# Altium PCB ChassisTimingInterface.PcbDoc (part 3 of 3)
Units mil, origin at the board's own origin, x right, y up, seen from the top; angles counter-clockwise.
Board outline 3400 x 6000 mil, 8 copper layers (Top Layer, GND, VDD, Mid-Layer 1, VCCAUX, Mid-Layer 2, MidLayer3, Bottom Layer), stack 62.1 mil thick; 229 components, 254 nets, 1249 pads, 708 vias.
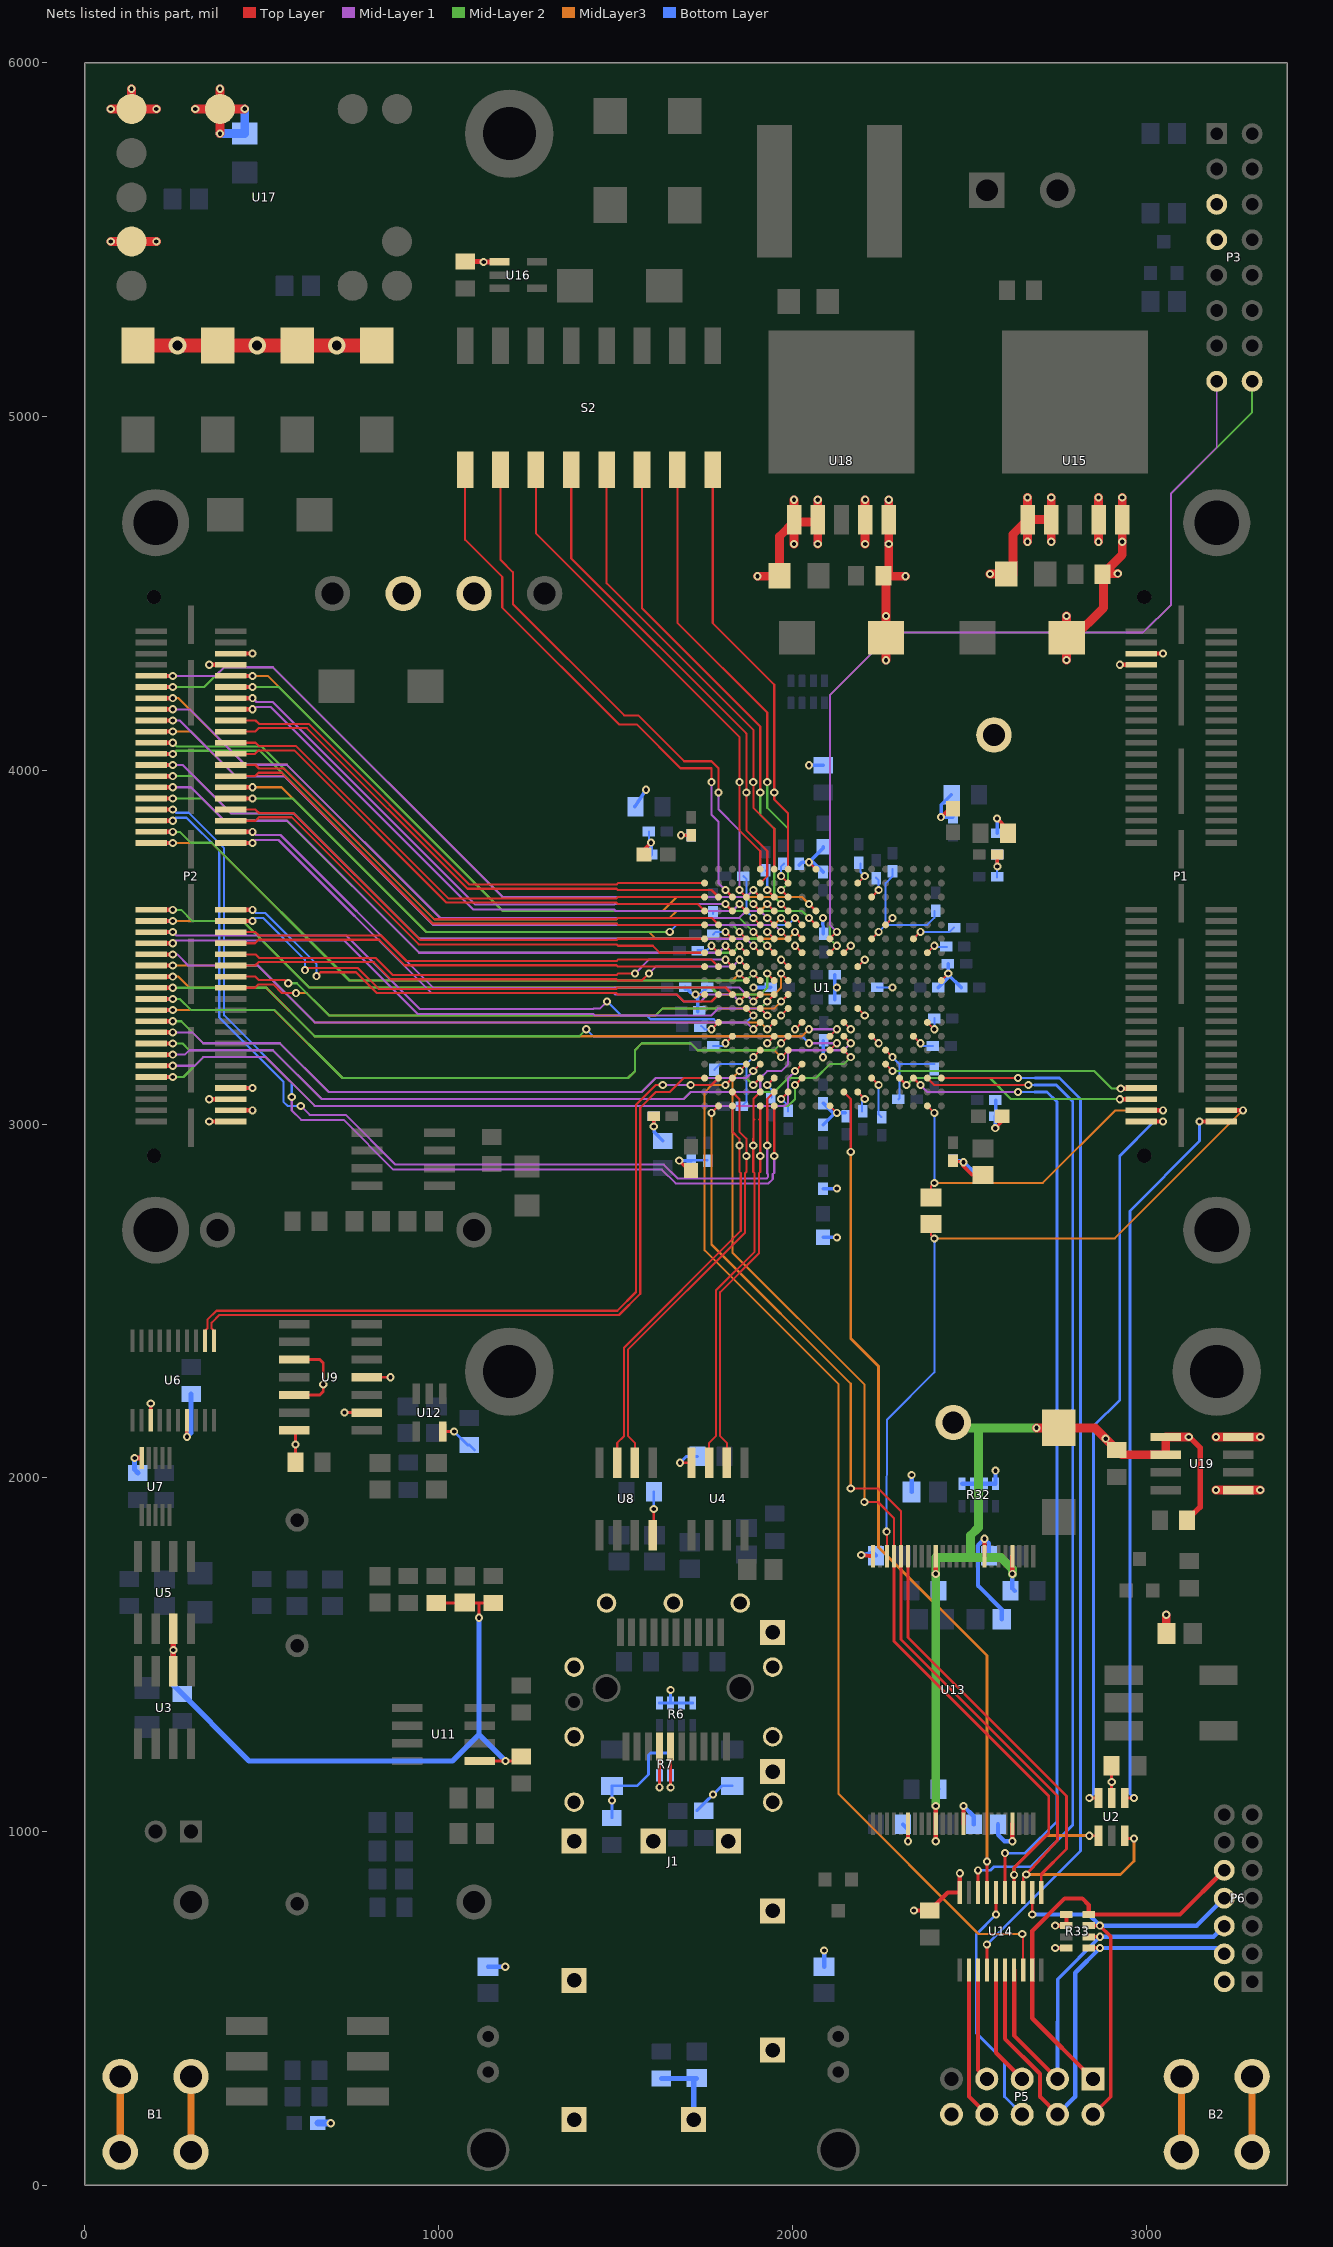
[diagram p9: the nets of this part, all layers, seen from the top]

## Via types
v1: diameter 23, hole 12, Top Layer to Bottom Layer, 669 vias
v2: diameter 23, hole 12.01, Top Layer to Bottom Layer, 33 vias
v3: diameter 50, hole 28, Top Layer to Bottom Layer, 6 vias

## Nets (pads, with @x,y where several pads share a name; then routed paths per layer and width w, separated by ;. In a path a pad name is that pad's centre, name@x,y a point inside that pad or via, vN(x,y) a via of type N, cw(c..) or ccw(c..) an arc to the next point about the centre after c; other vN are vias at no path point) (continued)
S33_48.S37_N: P2.27 U1.J13 | length 1605.9
  Top Layer w6: P2.27@412.78,3416.55 482.43,3416.55 492.18,3406.8 565,3406.8 573.8,3398 v1(574.8,3398) ; v1(1929.15,3346.46) U1.J13@1948.84,3366.14
  Mid-Layer 2 w6: v1(574.8,3398) 599.09,3398 690,3307.09 1515.75,3307.09 1535.43,3307.09 1614.17,3307.09 1633.86,3326.77 1909.47,3326.77 v1(1929.15,3346.46)
S33_48.S37_P: P2.25 U1.J12 | length 1648.7
  Top Layer w6: P2.25@412.78,3385.05 481.07,3385.05 490.82,3394.8 532.38,3394.8 557.18,3370 v1(596.8,3370) ; v1(1968.52,3346.46) U1.J12@1988.21,3366.14
  Mid-Layer 2 w6: v1(596.8,3370) v1@605.26,3370
  MidLayer3 w6: v1(596.8,3370) 627.09,3370 690,3307.09 1515.75,3307.09 1535.43,3307.09 1614.17,3307.09 1633.86,3326.77 1948.84,3326.77 v1(1968.52,3346.46)
S33_48.S38_N: P2.29 U1.L15 | length 1515.6
  Top Layer w6: P2.29@412.78,3448.03 481.07,3448.03 490.82,3457.78 816.58,3457.78 865.01,3409.36 1502.95,3409.36 1506.8,3405.51 1515.75,3405.51 1535.43,3405.51 1574.8,3405.51 v1(1594.49,3425.2) ; v1(1850.41,3464.57) U1.L15@1870.1,3444.88
  Mid-Layer 1 w6: v1(1594.49,3425.2) 1614.17,3444.88 1830.72,3444.88 v1(1850.41,3464.57)
S33_48.S38_P: P2.31 U1.L16 | length 1468
  Top Layer w6: P2.31@412.78,3479.53 482.43,3479.53 492.18,3469.78 821.56,3469.78 869.98,3421.36 1502.95,3421.36 1506.79,3425.2 ; 1506.89,3425.2 1515.75,3425.2 1535.43,3425.2 v1(1555.12,3425.2) ; v1(1811.04,3464.57) U1.L16@1830.73,3444.88
  Mid-Layer 1 w6: v1(1555.12,3425.2) 1594.5,3464.57 v1(1811.04,3464.57)
S33_48.S39_N: P2.35 U1.L17 | length 1422.1
  Top Layer w6: P2.35@412.78,3542.53 482.43,3542.53 492.18,3532.78 837.3,3532.78 909.26,3460.82 1502.95,3460.82 ; 1502.95,3460.73 1506.79,3464.57 ; 1506.89,3464.57 1515.75,3464.57 1535.43,3464.57 1771.67,3464.57 U1.L17@1791.36,3444.88
S33_48.S39_P: P2.33 U1.L18 | length 1374.6
  Top Layer w6: P2.33@412.78,3511.03 481.07,3511.03 490.82,3520.78 832.32,3520.78 904.29,3448.82 1502.95,3448.82 ; 1502.95,3448.73 1506.8,3444.88 1515.75,3444.88 1535.43,3444.88 U1.L18@1751.99,3444.88
S33_48.S40_N: P2.37 U1.J16 | length 1536.6
  Top Layer w6: v1(622,3435) 628.13,3441.13 771.46,3441.13 830.61,3381.99 1502.95,3381.99 1506.79,3385.83 ; 1506.89,3385.83 1515.75,3385.83 1535.43,3385.83 1811.04,3385.83 U1.J16@1830.73,3366.14
  Top Layer w12: P2.37@412.78,3574.02 v1(473.98,3574.02)
  Bottom Layer w6: v1(473.98,3574.02) 482.52,3582.55 503.95,3582.55 622,3464.5 v1(622,3435)
S33_48.S40_P: P2.39 U1.J17 | length 1522.8
  Top Layer w6: v1(655,3418) 666.13,3429.13 766.49,3429.13 825.64,3369.99 1502.95,3369.99 1506.8,3366.14 1515.75,3366.14 1535.43,3366.14 1673.23,3366.14 1692.91,3346.46 1771.67,3346.46 U1.J17@1791.36,3366.14
  Top Layer w12: P2.39@412.78,3605.52 v1(473.98,3605.52)
  Bottom Layer w6: v1(473.98,3605.52) 482.95,3596.55 509.75,3596.55 655,3451.3 v1(655,3418)
S33_48.S41_N: P2.43 U1.J14 | length 1704.9
  Top Layer w6: v1(1889.78,3346.46) U1.J14@1909.47,3366.14
  Top Layer w12: P2.43@412.78,3825.98 v1(473.98,3825.98)
  Mid-Layer 1 w6: v1(473.98,3825.98) 482.97,3817 553.08,3817 986,3384.08 1496.06,3384.08 1497.81,3385.83 1515.75,3385.83 1535.43,3385.83 1850.41,3385.83 v1(1889.78,3346.46)
S33_48.S41_P: P2.41 U1.J15 | length 1674.4
  Top Layer w6: v1(1850.41,3346.46) U1.J15@1870.1,3366.14
  Top Layer w12: P2.41@412.78,3794.48 v1(473.98,3794.48)
  Mid-Layer 1 w6: v1(473.98,3794.48) 482.5,3803 547.28,3803 980.2,3370.08 1496.06,3370.08 1500,3366.14 1515.75,3366.14 1535.43,3366.14 1673.23,3366.14 1692.91,3346.46 1741.46,3346.46 1761.14,3366.14 1830.72,3366.14 v1(1850.41,3346.46)
S33_48.S42_N: P2.45 U1.M18 | length 1501.9
  Top Layer w6: P2.45@412.78,3857.47 482.43,3857.47 492.18,3867.22 584.32,3867.22 943.75,3507.78 1502.95,3507.78 1506.8,3503.94 1515.75,3503.94 1535.43,3503.94 1555.12,3503.94 1605.32,3503.93 1625,3484.25 U1.M18@1751.99,3484.25
S33_48.S42_P: P2.47 U1.N18 | length 1493.6
  Top Layer w6: P2.47@412.78,3888.97 482.43,3888.97 492.18,3879.22 589.29,3879.22 948.72,3519.78 1502.95,3519.78 1506.79,3523.62 ; 1506.89,3523.62 1515.75,3523.62 1535.44,3523.62 U1.N18@1751.99,3523.62
S33_48.S43_N: P2.51 U1.N11 | length 1808.5
  Top Layer w6: v1(2007.89,3543.31) U1.N11@2027.58,3523.62
  Top Layer w12: P2.51@412.78,3951.97 v1(473.98,3951.97)
  MidLayer3 w6: v1(473.98,3951.97) 555.91,3951.97 964.57,3543.31 1515.75,3543.31 1535.43,3543.31 1594.49,3543.31 1614.17,3523.62 1988.21,3523.62 v1(2007.89,3543.31)
S33_48.S43_P: P2.49 U1.P11 | length 1795.5
  Top Layer w6: v1(2007.89,3582.68) U1.P11@2027.58,3562.99
  Top Layer w12: P2.49@412.78,3920.47 v1(473.98,3920.47)
  Mid-Layer 2 w6: v1(473.98,3920.47) 587.41,3920.47 964.57,3543.31 1515.75,3543.31 1535.43,3543.31 v1(1653.54,3543.31)
  Bottom Layer w6: v1(1653.54,3543.31) 1673.23,3562.99 1988.21,3562.99 v1(2007.89,3582.68)
S33_48.S44_N: P2.53 U1.P18 | length 1521.4
  Top Layer w6: P2.53@412.78,3983.45 481.07,3983.45 490.82,3993.2 556.76,3993.2 983.12,3566.84 1502.95,3566.84 1506.8,3562.99 1515.75,3562.99 1535.43,3562.99 U1.P18@1751.99,3562.99
S33_48.S44_P: P2.55 U1.P17 | length 1568.9
  Top Layer w6: P2.55@412.78,4014.95 482.43,4014.95 492.18,4005.2 561.73,4005.2 988.09,3578.84 1502.95,3578.84 1506.79,3582.68 ; 1506.89,3582.68 1515.75,3582.68 1535.43,3582.68 1771.67,3582.68 U1.P17@1791.36,3562.99
S33_48.S45_N: P2.59 U1.T18 | length 1523
  Top Layer w6: P2.59@412.78,4077.95 482.43,4077.95 492.18,4068.2 597.15,4068.2 1027.46,3637.89 1502.95,3637.89 1506.79,3641.73 ; 1506.89,3641.73 1515.75,3641.73 1535.43,3641.73 1584.65,3641.73 U1.T18@1751.99,3641.73
S33_48.S45_P: P2.57 U1.R18 | length 1596.2
  Top Layer w6: P2.57@412.78,4046.45 481.07,4046.45 490.82,4056.2 592.18,4056.2 1022.49,3625.89 1502.95,3625.89 1506.8,3622.05 1515.75,3622.05 1535.43,3622.04 1732.31,3622.04 U1.R18@1751.99,3602.36 ; 1539.37,3622.05 1604.33,3622.05
S33_48.S46_N: P2.61 U1.T17 | length 1629.6
  Top Layer w6: P2.61@412.78,4109.43 481.07,4109.43 490.82,4119.18 627.63,4119.18 1081.55,3665.26 1502.95,3665.26 1506.8,3661.42 1515.75,3661.42 1535.43,3661.42 1604.33,3661.42 ; 1555.12,3661.42 1771.67,3661.42 U1.T17@1791.36,3641.73
S33_48.S46_P: P2.63 U1.U18 | length 1532.8
  Top Layer w6: P2.63@412.78,4140.93 482.43,4140.93 492.18,4131.18 632.6,4131.18 1086.52,3677.26 1502.95,3677.26 1506.79,3681.1 ; 1506.89,3681.1 1515.75,3681.1 1535.43,3681.1 U1.U18@1751.99,3681.1
S33_48.S47_N: P2.67 U1.R16 | length 1668.6
  Top Layer w6: v1(1811.04,3622.05) U1.R16@1830.73,3602.36
  Top Layer w12: P2.67@412.78,4203.93 v1(473.98,4203.93)
  Mid-Layer 1 w6: v1(473.98,4203.93) 485,4192.91 531.5,4192.91 1104.11,3620.3 1496.06,3620.3 1497.81,3622.05 1515.75,3622.05 1535.43,3622.05 v1(1811.04,3622.05)
S33_48.S47_P: P2.65 U1.R15 | length 1715.1
  Top Layer w6: v1(1850.41,3622.05) U1.R15@1870.1,3602.36
  Top Layer w12: P2.65@412.78,4172.43 v1(473.98,4172.43)
  Mid-Layer 1 w6: v1(473.98,4172.43) 480.46,4178.91 525.7,4178.91 1098.31,3606.3 1496.06,3606.3 1500,3602.36 1515.75,3602.36 1535.43,3602.36 1830.73,3602.36 v1(1850.41,3622.05)
S33_48.S48_N: P2.69 U1.P10 | length 1932.7
  Top Layer w6: v1(2047.26,3582.68) U1.P10@2066.95,3562.99
  Top Layer w12: P2.69@412.78,4235.42 v1(473.98,4235.42)
  Mid-Layer 2 w6: v1(473.98,4235.42) 548.05,4235.42 1181.1,3602.36 1515.75,3602.36 1535.43,3602.36 2027.57,3602.36 v1(2047.26,3582.68)
S33_48.S48_P: P2.71 U1.R10 | length 1962
  Top Layer w6: v1(2047.26,3622.05) U1.R10@2066.95,3602.36
  Top Layer w12: P2.71@412.78,4266.92 v1(473.98,4266.92)
  MidLayer3 w6: v1(473.98,4266.92) 516.55,4266.92 1181.1,3602.36 1515.75,3602.36 1535.43,3602.36 1633.86,3602.36 1673.23,3641.73 2027.57,3641.73 v1(2047.26,3622.05)
S49_64.S49_N: P2.12 U1.D11 | length 1997.4
  Top Layer w6: v1(2007.89,3149.61) U1.D11@2027.58,3169.29
  Top Layer w12: P2.12@187.22,3164.58 v1(248.42,3164.58)
  Mid-Layer 1 w6: v1(248.42,3164.58) 310.25,3164.58 334.65,3188.98 511.81,3188.98 649.61,3051.18 1515.75,3051.18 1535.43,3051.18 1979.33,3051.18 1988.19,3060.04 1988.19,3129.9 v1(2007.89,3149.61)
S49_64.S49_P: P2.10 U1.C11 | length 1976.3
  Top Layer w6: v1(2007.89,3110.24) U1.C11@2027.58,3129.92
  Top Layer w12: P2.10@187.22,3133.08 v1(248.42,3133.08)
  Mid-Layer 2 w6: v1(248.42,3133.08) 278.75,3133.08 334.65,3188.98 511.81,3188.98 649.61,3051.18 1515.75,3051.18 1535.43,3051.18 1988.19,3051.18 2007.89,3070.88 v1(2007.89,3110.24)
S49_64.S50_N: P2.14 U1.F8 | length 2168.9
  Top Layer w6: U1.F8@2145.69,3248.03 v1(2165.37,3228.35)
  Top Layer w12: P2.14@187.22,3196.07 v1(248.42,3196.07)
  Mid-Layer 1 w6: v1(248.42,3196.07) 282.68,3196.07 295.28,3208.66 531.5,3208.66 669.29,3070.87 1515.75,3070.87 1535.43,3070.87 1692.91,3070.87 1712.6,3090.55 1900.59,3090.55 1909.45,3099.41 1909.45,3129.92 1929.13,3149.61 1968.52,3149.61 1988.19,3169.29 1988.19,3199.19 1997.66,3208.66 2145.67,3208.66 v1(2165.37,3228.35)
S49_64.S50_P: P2.16 U1.E8 | length 2119.8
  Top Layer w6: U1.E8@2145.69,3208.66 v1(2165.36,3188.98)
  Top Layer w12: P2.16@187.22,3227.57 v1(248.42,3227.57)
  Mid-Layer 2 w6: v1(248.42,3227.57) 276.37,3227.57 295.28,3208.66 531.5,3208.66 669.29,3070.87 1515.75,3070.87 1535.43,3070.87 1692.91,3070.87 1712.6,3090.55 1948.84,3090.55 1988.21,3129.92 2066.93,3129.92 2106.3,3169.29 2145.67,3169.29 v1(2165.36,3188.98)
S49_64.S51_N: P2.20 U1.C14 | length 1837.7
  Top Layer w6: v1(1889.76,3110.24) U1.C14@1909.45,3129.92
  Top Layer w12: P2.20@187.22,3290.57 v1(248.42,3290.57)
  Mid-Layer 2 w6: v1(248.42,3290.57) 272.43,3290.57 334.65,3228.35 551.18,3228.35 688.98,3090.55 1515.75,3090.55 1535.43,3090.55 1574.8,3090.55 1614.17,3129.92 1870.08,3129.92 v1(1889.76,3110.24)
S49_64.S51_P: P2.18 U1.D14 | length 1824.6
  Top Layer w6: v1(1889.76,3149.61) U1.D14@1909.45,3169.29
  Top Layer w12: P2.18@187.22,3259.07 v1(248.42,3259.07)
  Mid-Layer 1 w6: v1(248.42,3259.07) 303.93,3259.07 334.65,3228.35 551.18,3228.35 688.98,3090.55 1515.75,3090.55 1535.43,3090.55 1574.8,3090.55 1614.17,3129.92 1870.08,3129.92 v1(1889.76,3149.61)
S49_64.S52_N: P2.22 U1.E12 | length 1980.4
  Top Layer w6: v1(1968.5,3188.98) U1.E12@1988.19,3208.66
  Top Layer w12: P2.22@187.22,3322.05 v1(248.42,3322.05)
  MidLayer3 w6: v1(248.42,3322.05) 536.22,3322.05 728.35,3129.92 1515.75,3129.92 1535.43,3129.92 1555.12,3149.61 1555.12,3208.66 1574.8,3228.35 1712.6,3228.35 1732.28,3208.66 1948.82,3208.66 v1(1968.5,3188.98)
S49_64.S52_P: P2.24 U1.F12 | length 1993.4
  Top Layer w6: v1(1968.52,3228.35) U1.F12@1988.21,3248.03
  Top Layer w12: P2.24@187.22,3353.55 v1(248.42,3353.55)
  Mid-Layer 2 w6: v1(248.42,3353.55) 268.5,3353.55 300.2,3321.85 536.42,3321.85 728.35,3129.92 1515.75,3129.92 1535.43,3129.92 1555.12,3149.61 1555.12,3208.66 1574.8,3228.35 1712.6,3228.35 1732.28,3208.66 1948.84,3208.66 v1(1968.52,3228.35)
S49_64.S53_N: P2.28 U1.F9 | length 2044.6
  Top Layer w6: U1.F9@2106.32,3248.03 v1(2126,3267.72)
  Top Layer w12: P2.28@187.22,3416.55 v1(248.42,3416.55)
  Mid-Layer 1 w6: v1@2047.24,3267.72 v1(2126,3267.72)
  MidLayer3 w6: v1(248.42,3416.55) 264.55,3416.55 295.28,3385.83 511.81,3385.83 649.61,3248.03 1515.75,3248.03 1535.43,3248.03 2027.58,3248.03 v1(2047.26,3267.72)
S49_64.S53_P: P2.26 U1.E9 | length 2047.8
  Top Layer w6: U1.E9@2106.32,3208.66 v1(2126,3228.35)
  Top Layer w12: P2.26@187.22,3385.05 v1(248.42,3385.05)
  Mid-Layer 1 w6: v1(2047.26,3228.35) v1(2126,3228.35)
  Mid-Layer 2 w6: v1(248.42,3385.05) 512.59,3385.05 649.61,3248.03 1397.64,3248.03 v1(1417.32,3267.72)
  Bottom Layer w6: v1(1417.32,3267.72) 1437.01,3248.03 1515.75,3248.03 1535.43,3248.03 2027.57,3248.03 v1(2047.26,3228.35)
S49_64.S54_N: P2.30 U1.G13 | length 1844.5
  Top Layer w6: v1(1929.15,3267.72) U1.G13@1948.84,3287.4
  Top Layer w12: P2.30@187.22,3448.03 v1(248.42,3448.03)
  MidLayer3 w6: v1(248.42,3448.03) 488.97,3448.03 649.61,3287.4 1515.75,3287.4 1535.43,3287.4 1909.46,3287.4 v1(1929.15,3267.72)
S49_64.S54_P: P2.32 U1.G14 | length 1818.1
  Top Layer w6: v1(1889.78,3267.72) U1.G14@1909.47,3287.4
  Top Layer w12: P2.32@187.22,3479.53 v1(248.42,3479.53)
  Mid-Layer 1 w6: v1(248.42,3479.53) 260.62,3479.53 292.16,3448 489.01,3448 649.61,3287.4 1515.75,3287.4 1535.43,3287.4 1870.09,3287.4 v1(1889.78,3267.72)
S49_64.S55_N: P2.36 U1.H15 | length 1862
  Top Layer w6: U1.H15@1870.1,3326.77 v1(1889.78,3307.09)
  Top Layer w12: P2.36@187.22,3542.53 v1(248.42,3542.53)
  Mid-Layer 1 w6: v1(248.42,3542.53) 257.95,3533 738.65,3533 946.63,3325.02 1437.01,3325.02 1438.76,3326.77 1456.69,3326.77 v1(1476.38,3346.46)
  Bottom Layer w6: v1(1476.38,3346.46) 1515.75,3307.09 1535.43,3307.09 1587.91,3307.09 1599,3296 1778,3296 1786.6,3287.4 1870.1,3287.4 v1(1889.78,3307.09)
S49_64.S55_P: P2.34 U1.H14 | length 1877.2
  Top Layer w6: U1.H14@1909.47,3326.77 v1(1929.15,3307.09)
  Top Layer w12: P2.34@187.22,3511.03 v1(248.42,3511.03)
  Mid-Layer 1 w6: v1(248.42,3511.03) 256.38,3519 732.85,3519 940.83,3311.02 1437.01,3311.02 1440.94,3307.09 1456.69,3307.09 1515.75,3307.09 1535.43,3307.09 1771.65,3307.09 1791.34,3326.77 1909.47,3326.77 v1(1929.15,3307.09)
S49_64.S56_N: P2.38 U1.K12 | length 1942.8
  Top Layer w6: v1(1968.52,3425.2) U1.K12@1988.21,3405.51
  Top Layer w12: P2.38@187.22,3574.02 v1(248.42,3574.02)
  MidLayer3 w6: v1(248.42,3574.02) 445.98,3574.02 634.17,3385.83 1515.75,3385.83 1535.43,3385.83 1771.65,3385.83 1791.34,3366.14 1948.82,3366.14 1968.52,3385.84 v1(1968.52,3425.2)
S49_64.S56_P: P2.40 U1.K13 | length 1916.4
  Top Layer w6: v1(1929.15,3425.2) U1.K13@1948.84,3405.51
  Top Layer w12: P2.40@187.22,3605.52 v1(248.42,3605.52)
  Mid-Layer 2 w6: v1(248.42,3605.52) 272.44,3605.52 303.94,3574.02 445.98,3574.02 634.17,3385.83 1515.75,3385.83 1535.43,3385.83 1771.65,3385.83 1791.34,3366.14 1909.45,3366.14 1929.15,3385.84 v1(1929.15,3425.2)
S49_64.S57_N: P2.44 U1.K14 | length 1912.7
  Top Layer w6: v1(1889.78,3425.2) U1.K14@1909.47,3405.51
  Top Layer w12: P2.44@187.22,3825.98 v1(248.42,3825.98)
  Mid-Layer 2 w6: v1(248.42,3825.98) 268.5,3825.98 299.49,3795 358.54,3795 748.03,3405.51 1515.75,3405.51 1535.43,3405.51 1870.1,3405.51 v1(1889.78,3425.2)
S49_64.S57_P: P2.42 U1.K15 | length 1860.3
  Top Layer w6: v1(1850.41,3425.2) U1.K15@1870.1,3405.51
  Top Layer w12: P2.42@187.22,3794.48 v1(248.42,3794.48)
  MidLayer3 w6: v1(248.42,3794.48) 359.06,3794.48 748.03,3405.51 1515.75,3405.51 1535.43,3405.51 1830.73,3405.51 v1(1850.41,3425.2)
S49_64.S58_N: P2.46 U1.B13 | length 2730.9
  Top Layer w6: v1(1929.13,2938.97) 1929.13,3070.85 U1.B13@1948.84,3090.55
  Top Layer w12: P2.46@187.22,3857.47 v1(248.42,3857.47)
  Mid-Layer 1 w6: v1(610.24,3051.18) 635.61,3025.81 737.19,3025.81 878,2885 1637,2885 1676,2846 1927,2846 1930.88,2849.88 1930.88,2858.27 1929.13,2860.02 1929.13,2877.95 1929.13,2893.7 v1(1929.13,2938.97)
  Bottom Layer w6: v1(248.42,3857.47) 256.95,3866 287.43,3866 379.7,3773.73 379.7,3301.29 560.97,3120.02 560.97,3088.03 ; 561,3088 561,3063 572.82,3051.18 v1(610.24,3051.18)
S49_64.S58_P: P2.48 U1.A13 | length 2731.5
  Top Layer w6: v1(1948.81,2909.44) U1.A13@1948.84,3051.18
  Top Layer w12: P2.48@187.22,3888.97 v1(248.42,3888.97)
  Mid-Layer 1 w6: v1(584.87,3076.55) 584.87,3038.13 611.19,3011.81 731.39,3011.81 872.2,2871 1631.2,2871 1670.2,2832 1932.8,2832 1944.88,2844.08 1944.88,2858.27 1948.82,2862.2 1948.82,2877.95 1948.81,2893.71 v1(1948.81,2909.44)
  Bottom Layer w6: v1(248.42,3888.97) 257.38,3880 293.23,3880 393.7,3779.53 393.7,3307.09 584.87,3115.92 v1(584.87,3076.55)
S49_64.S59_N: P2.52 U1.M16 | length 1853.6
  Top Layer w6: v1(1811.04,3503.94) U1.M16@1830.73,3484.25
  Top Layer w12: P2.52@187.22,3951.97 v1(248.42,3951.97)
  Mid-Layer 1 w6: v1(248.42,3951.97) 300,3951.97 394.5,3857.47 571.67,3857.47 944.88,3484.25 1515.75,3484.25 1535.43,3484.25 1791.36,3484.25 v1(1811.04,3503.94)
S49_64.S59_P: P2.50 U1.M15 | length 1879.9
  Top Layer w6: v1(1850.41,3503.94) U1.M15@1870.1,3484.25
  Top Layer w12: P2.50@187.22,3920.47 v1(248.42,3920.47)
  Mid-Layer 2 w6: v1(248.42,3920.47) 331.5,3920.47 393.7,3858.27 570.87,3858.27 944.88,3484.25 1515.75,3484.25 1535.43,3484.25 1830.73,3484.25 v1(1850.41,3503.94)
S49_64.S60_N: P2.54 U1.M13 | length 1968.4
  Top Layer w6: v1(1929.15,3503.94) U1.M13@1948.84,3484.25
  Top Layer w12: P2.54@187.22,3983.45 v1(248.42,3983.45)
  Mid-Layer 2 w6: v1(248.42,3983.45) 307.89,3983.45 413.39,3877.95 590.55,3877.95 944.88,3523.62 1515.75,3523.62 1535.43,3523.62 1909.47,3523.62 v1(1929.15,3503.94)
S49_64.S60_P: P2.56 U1.M14 | length 1942.1
  Top Layer w6: v1(1889.78,3503.94) U1.M14@1909.47,3484.25
  Top Layer w12: P2.56@187.22,4014.95 v1(248.42,4014.95)
  Mid-Layer 1 w6: v1(248.42,4014.95) 276.39,4014.95 413.39,3877.95 590.55,3877.95 944.88,3523.62 1515.75,3523.62 1535.43,3523.62 1870.09,3523.62 v1(1889.78,3503.94)
S49_64.S61_N: P2.60 U1.N14 | length 1955
  Top Layer w6: v1(1889.78,3543.31) U1.N14@1909.47,3523.62
  Top Layer w12: P2.60@187.22,4077.95 v1(248.42,4077.95)
  Mid-Layer 2 w6: v1(248.42,4077.95) 259.25,4067.12 499.81,4067.12 988.09,3578.84 1502.95,3578.84 1506.79,3582.68 1515.75,3582.68 1535.43,3582.68 1850.41,3582.68 v1(1889.78,3543.31)
S49_64.S61_P: P2.58 U1.N15 | length 1906.6
  Top Layer w6: v1(1850.41,3543.31) U1.N15@1870.1,3523.62
  Top Layer w12: P2.58@187.22,4046.45 v1(248.42,4046.45)
  Mid-Layer 2 w6: v1(248.42,4046.45) 257.08,4055.12 494.84,4055.12 983.12,3566.84 1502.95,3566.84 1506.8,3562.99 1515.75,3562.99 1535.43,3562.99 1830.72,3562.99 v1(1850.41,3543.31)
S49_64.S62_N: P2.62 U1.P12 | length 2043.6
  Top Layer w6: v1(1968.52,3582.68) U1.P12@1988.21,3562.99
  Top Layer w12: P2.62@187.22,4109.43 v1(248.42,4109.43)
  MidLayer3 w6: v1(248.42,4109.43) 300.02,4109.43 426,3983.45 563.79,3983.45 984.25,3562.99 1515.75,3562.99 1535.43,3562.99 1948.84,3562.99 v1(1968.52,3582.68)
S49_64.S62_P: P2.64 U1.N12 | length 2056.7
  Top Layer w6: v1(1968.52,3543.31) U1.N12@1988.21,3523.62
  Top Layer w12: P2.64@187.22,4140.93 v1(248.42,4140.93)
  Mid-Layer 1 w6: v1(248.42,4140.93) 268.52,4140.93 426.45,3983 564.24,3983 984.25,3562.99 1515.75,3562.99 1535.43,3562.99 1948.83,3562.99 v1(1968.52,3543.31)
S49_64.S63_N: P2.68 U1.R13 | length 2043.4
  Top Layer w6: v1(1929.15,3622.05) U1.R13@1948.84,3602.36
  Top Layer w12: P2.68@187.22,4203.93 v1(248.42,4203.93)
  MidLayer3 w6: v1(248.42,4203.93) 264.57,4203.93 452.76,4015.75 570.87,4015.75 1003.94,3582.68 1515.75,3582.68 1535.43,3582.68 1653.54,3582.68 1673.23,3602.36 1909.47,3602.36 v1(1929.15,3622.05)
S49_64.S63_P: P2.66 U1.P13 | length 2030.4
  Top Layer w6: v1(1929.15,3582.68) U1.P13@1948.84,3562.99
  Top Layer w12: P2.66@187.22,4172.43 v1(248.42,4172.43)
  Mid-Layer 1 w6: v1(248.42,4172.43) 296.07,4172.43 452.76,4015.75 570.87,4015.75 1003.94,3582.68 1515.75,3582.68 1535.43,3582.68 1850.39,3582.68 1870.08,3602.36 1909.46,3602.36 v1(1929.15,3582.68)
S49_64.S64_N: P2.70 U1.R14 | length 2030.8
  Top Layer w6: v1(1889.78,3622.05) U1.R14@1909.47,3602.36
  Top Layer w12: P2.70@187.22,4235.42 v1(248.42,4235.42)
  Mid-Layer 2 w6: v1(248.42,4235.42) 337.78,4235.42 393.7,4291.34 531.5,4291.34 1181.1,3641.73 1515.75,3641.73 1535.43,3641.73 1870.09,3641.73 v1(1889.78,3622.05)
S49_64.S64_P: P2.72 U1.T14 | length 2017.7
  Top Layer w6: v1(1889.78,3661.42) U1.T14@1909.47,3641.73
  Top Layer w12: P2.72@187.22,4266.92 v1(248.42,4266.92)
  Mid-Layer 1 w6: v1(248.42,4266.92) 369.28,4266.92 393.7,4291.34 531.5,4291.34 1181.1,3641.73 1515.75,3641.73 1535.43,3641.73 1870.1,3641.73 v1(1889.78,3661.42)
SCL: J1.5 R7.1 | length 151
  Top Layer w8: v1(1656,1124) J1.5@1655.98,1240
  Bottom Layer w8: v1(1656,1124) R7.1@1656,1159
SDA: J1.4 R7.2 | length 150
  Top Layer w8: v1(1624.49,1124.49) J1.4@1624.49,1240
  Bottom Layer w8: v1(1624.49,1124.49) R7.2@1624.5,1159
SH0: B1.0 B2.0 C11.1 J1.21 J1.22 R8.1 | length 1075.1
  MidLayer3 w20: B1.0@100,93 B1.0@100,307 ; B1.0@300,93 B1.0@300,307 ; B2.0@3100,93 B2.0@3100,307 ; B2.0@3300,93 B2.0@3300,307
  Bottom Layer w8: R8.1@1720.94,293.54 R8.1@1729.02,301.61
  Bottom Layer w15: C11.1@1630,301.61 R8.1@1729.02,301.61 ; J1.21@1720.94,184.88 R8.1@1720.94,293.54
STCK: U1.B8 U14.17 | length 2430.9
  Top Layer w6: U1.B8@2145.69,3090.55 2165.37,3070.87 v1(2165.35,2921.26)
  Top Layer w8: U14.17@2550.39,827.24 v2(2550.39,914.61)
  MidLayer3 w6: 2165.35,2846.46 2165.35,2866.14 v1(2165.35,2921.26)
  MidLayer3 w8: 2165.35,2846.46 2165.35,2393.7 2244.09,2314.96 2244.09,1803.15 2550.39,1496.85 v2(2550.39,914.61)
STCK_EXT: P5.7 U14.3 | length 319.2
  Top Layer w12: U14.3@2524.8,608.74 2524.8,325.2 P5.7@2550,300
STDI: U1.C3 U14.15 | length 2762.9
  Top Layer w6: U1.C3@2342.54,3129.92 v1(2362.22,3110.24)
  Top Layer w8: U14.15@2601.58,827.24 v1(2601.58,938.42)
  Mid-Layer 1 w6: v1(2362.22,3110.24) 2381.91,3090.55 v1(2637.8,3090.55)
  Bottom Layer w6: v1(2637.8,3090.55) 2685.04,3090.55
  Bottom Layer w8: v1(2601.58,938.42) 2658.42,938.42 2748,1028 2748,3063.02 2720.47,3090.55 2704.72,3090.55 2685.04,3090.55
STDI_EXT: P5.5 U14.5 | length 339.4
  Top Layer w12: U14.5@2575.98,608.74 2575.98,374.02 P5.5@2650,300
STDO: U1.C1 U14.4 | length 2989.7
  Top Layer w6: U1.C1@2421.28,3129.92 v1(2637.79,3129.92)
  Top Layer w8: U14.4@2550,609.13 v2(2550,680)
  Bottom Layer w6: v1(2637.79,3129.92) 2687.01,3129.92
  Bottom Layer w8: v2(2550,680) 2815,945 2815,3070.83 2755.91,3129.92 2704.72,3129.92 2687.01,3129.92
STDO_EXT: P5.6 U14.16 | length 704.3
  Top Layer w8: v1(2575.98,764.68) U14.16@2575.98,827.24
  Bottom Layer w8: v1(2575.98,764.68) 2520,708.7 2520,430 2600,350 2600,250 P5.6@2650,200
STMS: U1.C2 U14.18 | length 2867.6
  Top Layer w6: U1.C2@2381.91,3129.92 2401.59,3110.24 v1(2667.32,3110.24)
  Top Layer w8: U14.18@2524.8,827.24 v1(2524.8,889.8)
  Bottom Layer w6: v1(2667.32,3110.24) 2685.03,3110.24
  Bottom Layer w8: v1@2525,890 2560,890 2570,900 2675,900 2793,1018 2793,3063.3 2746.06,3110.24 2704.72,3110.24 2685.03,3110.24
STMS_EXT: P5.8 U14.2 | length 429.8
  Top Layer w12: U14.2@2499.21,608.74 2499.21,250.79 P5.8@2550,200
SW1: S2.1 U1.T16 | length 1626.7
  Top Layer w6: S2.1@1075,4874.8 1075,4652 1180,4547 1180,4460 1510,4130 1560,4130 1684.09,4005.91 1771.65,4005.91 1771.65,3982.28 v1(1771.65,3966.54) ; v1(1811.04,3661.42) U1.T16@1830.73,3641.73
  Mid-Layer 1 w6: v1(1771.65,3966.54) 1771.65,3874.01 1791.33,3854.34 1791.35,3681.11 v1(1811.04,3661.42)
SW2: S2.2 U1.T15 | length 1589.7
  Top Layer w6: S2.2@1175,4874.8 1175,4595 1210,4560 1210,4470 1524.56,4155.44 1564.56,4155.44 1694.41,4025.59 1771.65,4025.59 1791.34,4005.91 1791.34,3982.28 v1(1791.34,3937.01) ; v1(1850.41,3661.42) U1.T15@1870.1,3641.73
  Mid-Layer 1 w6: v1(1791.34,3937.01) 1791.34,3889.76 1850.41,3830.69 v1(1850.41,3661.42)
SW3: S2.3 U1.V14 | length 1417.1
  Top Layer w6: S2.3@1275,4874.8 1275,4669.88 1850.39,4094.49 1850.39,4005.91 1850.39,3982.28 1850.39,3830.71 1909.47,3771.64 U1.V14@1909.47,3720.47
  other v1: 1850.39,3966.54
SW4: S2.4 U1.U14 | length 1431.2
  Top Layer w6: S2.4@1375,4874.8 1375,4599 1869.67,4104.33 ; 1870.08,4104.33 1870.08,4005.91 1870.08,3982.28 1870.08,3830.71 1929.15,3771.64 1929.15,3700.82 U1.U14@1909.47,3681.1
  other v1: 1870.08,3937.01
SW5: S2.5 U1.V13 | length 1350.6
  Top Layer w6: S2.5@1475,4874.8 1475,4528.94 1889.76,4114.17 1889.76,4005.91 1889.76,3982.28 1889.76,3893.7 1948.84,3834.63 U1.V13@1948.84,3720.47
  other v1: 1889.76,3966.54
SW6: S2.6 U1.R12 | length 1443.6
  Top Layer w6: S2.6@1575,4874.8 1575,4458.46 1909.45,4124.02 1909.45,4005.91 1909.45,3982.28 v1(1909.45,3937.01) ; v1(1968.52,3622.05) U1.R12@1988.21,3602.36
  Mid-Layer 2 w6: v1(1909.45,3937.01) 1909.45,3874.02 1948.83,3834.63 1948.83,3641.73 v1(1968.52,3622.05)
SW7: S2.7 U1.T12 | length 1379.1
  Top Layer w6: S2.7@1675,4874.8 1675,4417.52 1929.13,4163.39 1929.13,4005.91 1929.13,3982.28 v1(1929.13,3966.54) ; v1(1968.52,3661.42) U1.T12@1988.21,3641.73
  Mid-Layer 2 w6: v1(1929.13,3966.54) 1929.13,3893.7 1988.21,3834.63 1988.21,3681.1 v1(1968.52,3661.42)
SW8: S2.8 U1.V12 | length 1242.6
  Top Layer w6: S2.8@1775,4874.8 1775,4415.94 1948.82,4242.13 1948.82,4005.91 1948.82,3982.28 1948.82,3917.32 1988.21,3877.94 U1.V12@1988.21,3720.47
  other v1: 1948.82,3937.01
SW9: P1.6 U1.C4 | length 725.2
  Top Layer w6: U1.C4@2303.17,3129.92 v1(2322.84,3110.24)
  Top Layer w12: v1(2926.02,3070.08) P1.6@2987.22,3070.08
  Mid-Layer 2 w6: v1(2322.84,3110.24) 2342.52,3129.92 2559.06,3129.92 2618.11,3070.87 2925.23,3070.87 v1(2926.02,3070.08)
SW10: P1.8 U1.D5 | length 754.9
  Top Layer w6: U1.D5@2263.8,3169.29 v1(2283.48,3149.6)
  Top Layer w12: v1(2928.8,3100) P1.8@2990,3100
  Mid-Layer 2 w6: v1(2283.48,3149.6) 2854.34,3149.6 2903.94,3100 v1(2928.8,3100)
SYNC_N: U1.C17 U6.2 | length 2100
  Top Layer w6: U6.2@339.57,2387.2 339.57,2414.84 346.36,2421.64 346.36,2446.36 372,2472 1505.03,2472 1558,2524.97 1558,3054.06 1614.17,3110.24 v1(1633.86,3110.24) ; v1(1712.6,3110.24) 1771.67,3110.24 U1.C17@1791.36,3129.92
  Mid-Layer 1 w6: v1(1633.86,3110.24) v1(1712.6,3110.24)
SYNC_P: U1.C18 U6.1 | length 2042.4
  Top Layer w6: U6.1@365.16,2387.2 365.16,2414.84 358.36,2421.64 358.36,2438.36 380,2460 1510,2460 1570,2520 1570,3046.38 1614.17,3090.55 1653.54,3090.55 1692.91,3129.92 U1.C18@1751.99,3129.92
SYNCIN_N: U1.A14 U4.6 | length 1069.1
  Top Layer w6: U4.6@1815,2042.36 1815,2098.42 1796,2117.41 1796,2285.33 1796,2524.34 1905.6,2633.94 1905.6,2861.21 1909.45,2865.06 1909.45,2874.01 1909.44,2893.7 1909.44,2958.66 ; 1905.62,3012.5 1909.47,3016.34 ; 1909.47,2958.68 U1.A14@1909.47,3051.18
  other v1: 1909.44,2909.44
SYNCIN_P: U1.B14 U4.7 | length 1116.5
  Top Layer w6: U4.7@1765,2042.36 1765,2098.42 1784,2117.41 1784,2290.3 1784,2529.32 1893.6,2638.92 1893.6,2861.22 1889.76,2865.06 ; 1889.76,2865.15 1889.76,2874.01 1889.76,2893.7 1889.76,2958.66 ; 1889.78,2958.68 1889.78,3070.87 U1.B14@1909.47,3090.55 ; 1889.78,3016.34 1893.62,3012.5
  other v1: 1889.76,2938.97
SYNCLK_N: P3.16 U1.M9 | length 2541.6
  Top Layer w6: U1.M9@2106.32,3484.25 v1(2125.98,3503.94)
  Mid-Layer 2 w5: 2106.3,3996.06 2106.3,4212.6 2283.46,4389.76 2992.13,4389.76 3070.87,4468.5 3070.87,4783.46 3300,5012.6 P3.16@3300,5100
  Mid-Layer 2 w6: 2106.3,3996.06 2106.3,3976.38 2106.3,3523.62 v1(2125.98,3503.94)
SYNCLK_P: P3.15 U1.N9 | length 2460.8
  Top Layer w6: U1.N9@2106.32,3523.62 v1(2126,3543.31)
  Mid-Layer 1 w5: 2106.3,3996.06 2106.3,4212.6 2283.46,4389.76 2992.13,4389.76 3070.87,4468.5 3070.87,4783.46 3200,4912.6 P3.15@3200,5100
  Mid-Layer 1 w6: 2106.3,3996.06 2106.3,3976.38 2106.3,3563.01 v1(2126,3543.31)
SYNCOUT_N: U1.A16 U8.3 | length 1163.1
  Top Layer w6: U8.3@1505,2042.36 1505,2098.42 1524,2117.41 1524,2236.99 1524,2367.74 1854.23,2697.97 1854.23,2861.22 1850.39,2865.06 ; U1.A16@1830.73,3051.18 1830.73,2978.32 1850.39,2958.66 1850.39,2893.7 1850.39,2874.01 1850.39,2865.15
  other v1: 1850.39,2938.97
SYNCOUT_P: U1.B16 U8.2 | length 1210.8
  Top Layer w5.98: 1866.22,2692.99 1866.22,2861.22
  Top Layer w6: U8.2@1555,2042.36 1555,2098.42 1536,2117.41 1536,2232.02 1536,2362.77 1866.23,2693 ; U1.B16@1830.73,3090.55 1850.39,3070.89 1850.39,2978.34 1870.07,2958.66 1870.07,2893.7 1870.07,2874.01 1870.07,2865.06 1866.23,2861.21
  other v1: 1870.07,2909.44
TCK: U1.A17 U2.3 U13.20 U14.13 | length 3131
  Top Layer w6: v1(1771.65,3031.5) U1.A17@1791.36,3051.18 ; v1(2165.35,1969.49) 2243.11,1969.49 2307.17,1905.43 U13.20@2307.17,1777.79
  Top Layer w8: U13.20@2307.17,1777.79 2307.17,1542.83 2750,1100 2750,975 v1(2661.42,877.95) 2652.76,869.29 U14.13@2652.76,827.24 ; U2.3@2940,980 v1(2965.81,980)
  MidLayer3 w6: v1(1771.65,3031.5) 1771.65,2659.45 2165.35,2265.75 v1(2165.35,1969.49)
  MidLayer3 w8: v1(2661.42,877.95) 2927.76,877.76 2965.81,915.81 v1(2965.81,980)
TCK_B: P1.1 U2.4 | length 2086.5
  Top Layer w8: U2.4@2940.4,1094.15 v1(2966.21,1094.15)
  Top Layer w12: v1(3151.58,3007.1) P1.1@3212.78,3007.1
  Bottom Layer w8: v1(2966.21,1094.15) 2954.4,1105.96 2954.4,2754.4 3151.58,2951.58 v1(3151.58,3007.1)
TCK_EXT: P5.3 P6.6 R33.6 U14.7 | length 1207.2
  Top Layer w10: R33.6@2837.99,702.01 v1(2870,702.01)
  Top Layer w12: U14.7@2627.17,608.74 2627.17,422.83 P5.3@2750,300
  Bottom Layer w10: 2750,461.22 2750,582.01 v1(2870,702.01)
  Bottom Layer w12: P5.3@2750,300 2750,461.22 ; v1(2870,702.01) 3190.79,702.01 P6.6@3221.26,732.48
TDI_1: U13.19 U14.11 | length 1165.6
  Top Layer w8: U13.19@2326.85,1777.79 2326.85,1548.15 2775,1100 2775,950 2703.94,878.94 U14.11@2703.94,827.24
TDI_A: P1.3 R1.2 U13.22 | length 2082.9
  Top Layer w6: v1@2267.64,1847.44 2267.64,1777.95 U13.22@2267.8,1777.79 ; R1.2@2392,2717.6 2392,2686.15 v1(2401.58,2676.58)
  Top Layer w12: P1.3@3212.78,3038.58 v1(3273.98,3038.6)
  MidLayer3 w6: v1(2401.58,2676.58) 2911.96,2676.58 v1(3273.98,3038.6)
  Bottom Layer w6: v1(2266.73,1847.44) 2267.64,2164.29 2401.58,2298.23 v1(2401.58,2676.58)
TDI_B: P1.4 R1.1 U1.A2 | length 1063.9
  Top Layer w6: U1.A2@2381.91,3051.18 v1(2401.58,3031.49) ; R1.1@2392,2792.4 2392,2823.85 v1(2401.58,2833.42)
  Top Layer w12: P1.4@2987.22,3038.58 v1(3048.42,3038.6)
  MidLayer3 w6: v1(2401.58,2833.42) 2708.42,2833.42 2913.6,3038.6 v1(3048.42,3038.6)
  Bottom Layer w6: v1(2401.58,2833.42) v1(2401.58,3031.49)
TDI_EXT: P5.1 P6.10 R33.8 U14.9 | length 1156.5
  Top Layer w12: P5.1@2850,300 2678.35,471.65 2678.35,718.35 2770,810 2820,810 2837.99,792.01 R33.8@2837.99,765 3096.3,765 P6.10@3221.26,889.96
TDO: U1.C16 U14.8 | length 3021.7
  Top Layer w6: v1(1811.04,3110.24) U1.C16@1830.73,3129.92 ; v1(2650,710) 2652.76,707.24 U14.8@2652.76,608.74
  MidLayer3 w6: v1(1811.04,3110.24) 1772.64,3110.24 1751.97,3089.57 1751.97,2642.72 2130.91,2263.78 2130.91,1105.7 2526.61,710 v1(2650,710)
TDO_EXT: P5.2 P6.8 R33.7 U14.12 | length 1248.9
  Top Layer w8: v1(2678.35,764.68) U14.12@2678.35,827.24
  Top Layer w10: R33.7@2837.99,733.5 v1(2869.49,733.5) 2900,702.99 2900,610 2900,250 P5.2@2850,200
  Bottom Layer w12: v1(2678.35,764.68) 2838.31,764.68 v1(2869.49,733.5) 3143.54,733.5 P6.8@3221.26,811.22
TMS: U1.D15 U2.1 U13.21 U14.14 | length 3087.9
  Top Layer w5.98: U13.21@2287.48,1777.79 2287.48,1885.75
  Top Layer w6: v1(1850.41,3149.61) U1.D15@1870.1,3169.29 ; v1(2203.74,1931.1) 2242.13,1931.1 2287.48,1885.75
  Top Layer w8: U13.21@2287.48,1777.79 2287.48,1537.52 2725,1100 2725,995 2627.17,897.17 U14.14@2627.17,827.24 ; v1(2839.79,987.85) U2.1@2865.6,987.85
  MidLayer3 w6: v1(1850.41,3149.61) 1830.71,3129.9 1830.71,2636.81 2203.74,2263.78 v1(2203.74,1931.1)
  MidLayer3 w8: v1(2627.17,877.17) 2627.17,897.17 2718,988 v1@2839.79,988
TMS_B: P1.2 U2.6 | length 2101.4
  Top Layer w8: v1(2839.79,1094.15) U2.6@2865.6,1094.15
  Top Layer w12: P1.2@2987.22,3007.1 v1(3048.42,3007.1)
  Bottom Layer w8: v1(2839.79,1094.15) 2851.6,1105.96 2851.6,2145.67 2926.02,2220.09 2926.02,2910.27 3022.85,3007.1 v1(3048.42,3007.1)
TMS_EXT: P5.4 P6.4 R33.5 U14.6 | length 1380.7
  Top Layer w10: R33.5@2837.99,670.51 v1(2870,670.51)
  Top Layer w12: U14.6@2601.58,608.74 2601.58,413.42 2700,315 2700,250 P5.4@2750,200
  Bottom Layer w12: P5.4@2750,200 2800,250 2800,600.51 v1(2870,670.51) 3204.49,670.51 P6.4@3221.26,653.74
VCCAUX: C1.2 C32.1 C33.2 C34.2 C35.2 C36.2 C37.2 C54.1 C56.2 C83.2 C84.2 C85.2 C86.2 C87.2 C88.2 C89.2 C90.2 C91.2 C92.2 C93.2 C94.2 C95.2 C96.2 C97.2 C98.2 C99.2 C101.2 C102.2 C103.2 C104.2 C105.2 C106.2 C107.2 C108.2 C109.2 C110.2 C111.2 C112.2 C113.2 C114.2 C115.2 C116.2 C117.2 C118.2 C119.2 C120.2 C121.2 C122.2 C123.2 C124.2 C125.2 C126.2 C127.2 C128.2 C129.2 C130.2 C131.2 C132.2 C133.2 C134.2 C135.2 C136.2 P1.74 P1.76 P2.73 P2.75 P5.10 P6.2 R6.5 R6.6 R6.7 R6.8 R29.1 R31.1 R32.5 R32.6 R32.7 R32.8 R33.1 R33.2 R33.4 R35.2 TP5.1 U1.A9 U1.B7 U1.B12 U1.C6 U1.C13 U1.F3 U1.F16 U1.G2 U1.G8 U1.G11 U1.G17 U1.H7 U1.H12 U1.J18 U1.K1 U1.L7 U1.L12 U1.M2 U1.M8 U1.M11 U1.M17 U1.N3 U1.N16 U1.T6 U1.T13 U1.U7 U1.U12 U1.V10 U2.5 U13.8 U13.24 U13.30 U13.38 U13.45 U14.20 U18.4 U18.5 | length 5525.5
  Top Layer w5: v1(1726.38,3366.14) U1.J18@1751.99,3366.14
  Top Layer w6: v1(1771.67,3267.72) U1.G17@1791.36,3287.4 ; v1(1771.67,3503.94) U1.M17@1791.36,3484.25 ; v1(1811.04,3228.35) U1.F16@1830.73,3248.03 ; v1(1811.04,3543.31) U1.N16@1830.73,3523.62 ; v1(1929.15,3110.24) U1.C13@1948.84,3129.92 ; v1(1929.15,3661.42) U1.T13@1948.84,3641.73 ; v1(1968.52,3070.87) U1.B12@1988.21,3090.55 ; v1(1968.52,3307.09) U1.H12@1988.21,3326.77 ; v1(1968.52,3464.57) U1.L12@1988.21,3444.88 ; v1(1968.52,3700.79) U1.U12@1988.21,3681.1 ; v1(2007.89,3267.72) U1.G11@2027.58,3287.4 ; v1(2007.89,3503.94) U1.M11@2027.58,3484.25 ; v1@2047.26,3740.16 U1.V10@2066.95,3720.47 ; U1.A9@2106.32,3051.18 v1(2126,3031.5) ; U1.G8@2145.69,3287.4 v1(2165.37,3267.72) ; U1.M8@2145.69,3484.25 v1(2165.37,3503.94) ; U1.B7@2185.06,3090.55 v1(2204.74,3070.87) ; U1.H7@2185.06,3326.77 v1(2204.74,3307.09) ; U1.L7@2185.06,3444.88 v1(2204.74,3464.57) ; U1.U7@2185.06,3681.1 v1(2204.72,3700.79) ; U1.C6@2224.43,3129.92 v1(2244.11,3110.24) ; U1.T6@2224.43,3641.73 v1(2244.11,3661.42) ; U1.F3@2342.54,3248.03 v1(2362.22,3228.35) ; U1.N3@2342.54,3523.62 v1(2362.22,3543.31) ; U1.G2@2381.91,3287.4 v1(2401.59,3267.72) ; U1.M2@2381.91,3484.25 v1(2401.59,3503.94) ; U1.K1@2421.28,3405.51 v1(2440.96,3425.2)
  Top Layer w8: C1.2@2902.61,1185 2902.61,1078.79 U2.5@2903,1078.4
  Top Layer w10: C117.2@1580.59,3761.88 1580.59,3775.6 v1(1600.47,3795.47) ; v1(1608.47,2993.29) C116.2@1608.47,3021.88 ; v1(1680.47,2896.29) 1708.34,2868.42 C108.2@1714.06,2868.42 ; v1(1685.47,3816.29) C125.2@1714.06,3816.29 ; v1(2420.47,3867.47) 2444.34,3891.35 C126.2@2454.06,3891.35 ; C107.2@2454.06,2896.29 v1(2484,2892) 2482.65,2881.52 2507.88,2856.29 R35.2@2539.37,2856.29 ; v1(2573.65,2988.29) 2593.11,3007.76 C135.2@2593.11,3021.88 ; v1(2579.65,3728.29) C134.2@2579.65,3761.88
  Top Layer w12: v1(351.58,4298.42) P2.73@412.78,4298.42 ; P2.75@412.78,4329.92 v1(473.98,4329.92) ; v1(2194.88,1781.5) U13.24@2228.43,1777.79 ; v1(2326.85,972.24) U13.30@2326.85,1021.89 ; v1(2343.62,776.38) C32.1@2388.78,776.38 2439.65,827.24 U14.20@2473.62,827.24 v1(2473.62,881.65) ; U13.38@2484.33,1021.89 v1(2484.33,1071.53) ; U13.8@2543.39,1777.79 v1(2543.39,1827.44) ; v1(2622.13,972.24) U13.45@2622.13,1021.89 ; v1(2743.5,670.51) R33.4@2775,670.51 ; v1(2743.5,733.5) R33.2@2775,733.5 R33.1@2775,765 ; v1(2926.02,4298.42) P1.74@2987.22,4298.42 ; P1.76@2987.22,4329.92 v1(3048.42,4329.92)
  Top Layer w25: v1(2205.93,4639.84) v1(2205.93,4764.8) ; C56.2@2257.39,4548.66 v1(2319.87,4548.66) ; v1(2264.98,4311.18) C56.2@2264.98,4544.65 ; C56.2@2272.86,4554.8 v1(2272.86,4764.8)
  Bottom Layer w6: C122.2@1594.49,3826.76 1594.49,3803.14 v1@1602.36,3795.27 ; C106.2@1712.6,2897.63 C131.2@1759.84,2897.63 ; C121.2@1732.28,3492.12 1759.84,3492.12 v1(1771.67,3503.94) ; C119.2@1742.13,3277.55 1751.97,3267.71 v1(1771.67,3267.72) ; C85.2@1775.59,3220.46 1803.15,3220.46 v1(1811.04,3228.35) ; C86.2@1775.59,3535.42 1783.47,3543.3 v1(1811.04,3543.31) ; C87.2@1925.2,3716.53 1929.13,3712.59 v1(1929.15,3661.42) ; v1(1929.15,3110.24) 1940.95,3098.42 C84.2@1940.95,3074.79 ; v1(1968.52,3070.87) 1988.19,3051.17 C130.2@1988.19,3035.42 ; v1(1968.52,3700.79) 1968.5,3728.34 C110.2@1976.38,3736.21 ; C112.2@2192.91,3736.21 2192.91,3712.59 v1(2204.72,3700.79) ; C83.2@2196.85,3035.42 2196.85,3062.98 v1(2204.74,3070.87) ; C88.2@2236.22,3696.84 2244.1,3688.97 v1(2244.11,3661.42) ; v1(2244.11,3110.24) 2244.1,3027.55 C128.2@2251.97,3019.68 ; v1(2362.22,3228.35) 2370.08,3220.46 C90.2@2397.64,3220.46 ; v1(2362.22,3543.31) 2444.88,3543.3 C89.2@2456.69,3555.11 ; v1(2401.59,3267.72) C103.2@2401.58,3299.2 ; v1(2401.59,3503.94) 2405.51,3499.99 C101.2@2437.01,3499.99 ; C113.2@2578.74,3696.84 v1@2578.74,3728.34
  Bottom Layer w8: R6.5@1624.02,1362.99 R6.8@1718.5,1362.99 ; R6.6@1656,1362.99 v1(1656,1400)
  Bottom Layer w10: C118.2@1555.12,3897.63 v1(1586.69,3944.99) ; C114.2@1600.47,3761.88 v1@1600.47,3795.27 ; v1@1608.47,2996.05 C115.2@1608.47,3021.88 ; v1@1610.24,2996.05 1610.24,2976.37 C109.2@1633.86,2952.75 ; v1(1680.47,2896.29) C106.2@1714.06,2896.29 ; v1(1685.47,3816.29) C124.2@1714.06,3816.29 ; C96.2@1697.65,3381.11 C96.2@1697.65,3386.88 1732.3,3352.23 ; C120.2@1732.28,3316.92 1732.28,3346.46 1732.3,3359.72 C93.2@1759.47,3386.88 ; C111.2@2019.69,3732.27 2027.56,3740.15 v1@2047.24,3740.15 ; v1@2047.59,4014.27 C99.2@2088.06,4014.27 ; C95.2@2087.06,2997.47 v1@2121.08,3031.5 ; C91.2@2087.06,3059.29 2114.85,3031.5 v1(2126,3031.5) C129.2@2149.61,3031.49 ; C92.2@2087.06,3712.47 2059.37,3740.16 v1@2047.26,3740.16 ; C98.2@2088.06,3783.42 2088.06,3780.95 v1@2047.26,3740.16 ; C94.2@2412.65,3385.88 2440.96,3414.2 v1(2440.96,3425.2) C102.2@2440.95,3452.75 ; v1(2420.47,3867.47) C123.2@2454.06,3867.47 ; v1@2421.26,3867.12 2421.26,3902.55 C127.2@2449.8,3931.09 ; v1@2440.96,3422.38 C97.2@2477.47,3385.88 ; C105.2@2454.06,2896.29 v1@2480.32,2896.29 ; v1@2480.32,2897.63 2523.62,2854.32 C136.2@2539.37,2854.32 ; v1(2573.65,2988.29) C132.2@2573.65,3021.88 ; C132.2@2574.8,3019.68 C104.2@2574.8,3066.92 ; v1(2579.65,3728.29) C133.2@2579.65,3761.88
  Bottom Layer w12: v1(2194.88,1781.5) 2228.43,1787.83 C34.2@2236.42,1779.84 ; C36.2@2313.19,1019.84 2326.85,1006.18 v1(2326.85,972.24) ; R31.1@2337.4,1959.84 v1(2337.4,2007.44) ; R32.5@2480.32,1982.83 R32.8@2574.8,1982.83 v1(2574.8,2019.84) ; v1(2484.33,1071.53) 2513.19,1042.68 C37.2@2513.19,1019.84 ; C33.2@2556.42,1779.84 2556.42,1814.41 v1(2543.39,1827.44) 2524.8,1808.86 2524.8,1694.84 2592.21,1627.44 R29.1@2592.21,1599.84 ; C35.2@2581.61,1020 2581.61,990.39 2599.76,972.24 v1(2622.13,972.24)
  other v1: 2903,1140 2047.24,3740.16 2047.26,4014.27 2264.98,4436.14 2272.86,4639.84
VCCCONF: C38.2 C39.2 C40.2 C57.1 C58.1 C59.2 TP6.1 U13.4 U13.15 U13.34 U19.1 U19.2 | length 2757.5
  Top Layer w12: v1(2405.59,972.24) v1(2405.59,1071.53) ; v1(2405.59,1728.15) U13.15@2405.59,1777.79 ; v1(2622.13,1728.15) U13.4@2622.13,1777.79
  Top Layer w15: U19.1@3055.64,2115 3123,2115 3153,2085 3153,1916.61 C58.1@3116.39,1880
  Top Layer w25: v1(2690.52,2140.98) 2855.4,2140.98 2931.39,2065 U19.2@3055.64,2065 U19.1@3055.64,2115 v1(3121,2115)
  Mid-Layer 2 w25: v1(2405.59,1071.53) 2405.59,1774 2590,1774 2622.13,1741.87 v1(2622.13,1728.15) ; TP6.1@2455,2156 2470.02,2140.98 v1(2690.52,2140.98) ; 2503.94,1774 2503.94,1836.61 2526,1858.68 2526,2140.98
  Bottom Layer w12: C39.2@2400.39,1679.84 2405.59,1685.04 v1(2405.59,1728.15) ; v1(2405.59,1071.53) 2405.59,1112.24 C40.2@2413.19,1119.84 ; v1(2622.13,1728.15) 2622.13,1686.93 C38.2@2629.21,1679.84
  other v1: 2885.94,2110.45
VCCINT: C41.1 C43.2 C65.1 C66.1 C67.1 C68.1 C69.1 C70.1 C71.1 C72.1 C73.1 C74.2 C75.2 C76.2 C77.2 C78.2 C79.2 C80.2 C81.2 C82.2 TP3.1 U1.E5 U1.E14 U1.F6 U1.F13 U1.N6 U1.N13 U1.P5 U1.P14 U15.4 U15.5 | length 2504.8
  Top Layer w6: v1(1889.78,3188.98) U1.E14@1909.47,3208.66 ; v1(1889.78,3582.68) U1.P14@1909.47,3562.99 ; v1(1929.15,3228.35) U1.F13@1948.84,3248.03 ; v1(1929.15,3543.31) U1.N13@1948.84,3523.62 ; U1.F6@2224.43,3248.03 v1(2244.11,3228.35) ; U1.N6@2224.43,3523.62 v1(2244.11,3543.31) ; U1.E5@2263.8,3208.66 v1(2283.48,3188.98) ; U1.P5@2263.8,3562.99 v1(2283.48,3582.68)
  Top Layer w10: v1(2579.06,3863.88) 2609.44,3833.5 C82.2@2609.44,3821.88
  Top Layer w25: v1(2775.02,4311.52) 2775.02,4370 2790,4370 2880,4460 2880,4555 v1(2920,4556) ; C41.1@2775.02,4378 v1(2775.02,4436.48) ; v1(2865.93,4646.18) v1(2865.93,4771.14) ; C43.2@2877.39,4554 2932.86,4609.47 v1(2932.86,4771.14)
  Bottom Layer w6: C66.1@1775.59,3594.48 C66.1@1775.59,3598.42 1779.53,3602.35 1870.08,3602.35 ; C65.1@1779.53,3153.53 1795.28,3169.28 1870.08,3169.28 ; C69.1@1858.27,3051.17 1870.08,3062.98 1870.08,3169.28 ; C70.1@1862.21,3700.78 1870.08,3692.9 1870.08,3602.35 ; v1(1889.78,3188.98) 1870.08,3169.28 ; v1(1889.78,3582.68) 1870.08,3602.35 ; C75.2@2239.65,3386.88 2240.7,3385.83 v1(2283.46,3385.83) ; v1(2244.11,3543.31) v1(2283.48,3582.68) ; C67.1@2283.47,3720.46 2283.47,3700.78 2263.78,3681.09 2263.78,3562.98 2381.89,3562.98 2401.58,3582.67 C71.1@2401.58,3602.35 ; v1(2283.48,3188.98) 2303.15,3169.28 ; C72.1@2300.2,3069.87 2303.15,3072.83 2303.15,3169.28 ; C68.1@2401.58,3169.28 2303.15,3169.28
  Bottom Layer w10: v1(1890.06,3385.88) 1937.47,3385.88 C74.2@1938.47,3386.88 ; v1@2086.06,3584.88 C76.2@2088.06,3538.47 ; C73.1@2087.06,2679.42 v1@2126.47,2679.42 ; C80.2@2087.06,2817.29 v1@2126.47,2817.29 ; v1@2087.06,3188.88 C77.2@2088.06,3235.29 ; C79.2@2119.65,3351.88 C78.2@2119.65,3421.88 ; v1(2579.06,3863.88) C81.2@2579.65,3821.88
  other v1: 2126,2679.42 2126,2817.29 2086.56,3188.88 2125.98,3385.83 2086.76,3582.68 2932.86,4646.18
VDD: C6.2 C7.2 C26.1 C27.1 C28.1 C29.1 C30.2 C31.2 C42.2 C44.1 C45.1 C46.1 C47.1 C50.1 C55.2 C100.2 FR1.1 L1.2 L2.2 P2.1 P2.3 P2.5 P2.7 P3.5 P3.7 R5.2 R7.3 R7.4 R28.1 R36.2 TP4.1 U4.8 U6.13 U6.17 U7.10 U8.8 U9.2 U9.4 U9.10 U9.12 U9.14 U12.5 U15.1 U15.2 U16.1 U17.5 U17.6 U17.9 U18.1 U18.2 U19.5 U19.8 | length 4806.5
  Top Layer w8: U9.12@591.64,2234 664,2234 674,2244 674,2324 664,2334 U9.10@591.64,2334 ; C30.2@595.63,2044.02 U9.14@595.61,2130.02 ; v1(734,2184) U9.2@796.36,2184 ; U9.4@796.36,2284 v1(864,2284) ; U12.5@1011.4,2130.85 v1(1044,2130.85) ; U8.8@1608.39,1841.02 v1(1608.39,1911.61) ; v1(1682.36,2042.36) U4.8@1715,2042.36
  Top Layer w10: U6.13@186.02,2162.8 v2(186.02,2209.84) ; v2(288.39,2115.75) U6.17@288.39,2162.8
  Top Layer w12: v1(351.58,3007.1) P2.1@412.78,3007.1 ; v1(351.58,3070.08) P2.5@412.78,3070.08 ; P2.3@412.78,3038.58 v1(473.98,3038.6) ; P2.7@412.78,3101.58 v1(473.98,3101.58)
  Top Layer w14: v1(140.71,2055.71) U7.10@160.63,2055.71 ; C100.2@1075,5438.39 1126.42,5438.39 v1(1127.4,5437.4) U16.1@1171.85,5437.4
  Top Layer w25: v1(73,5495) v1(202,5495) ; v1(73,5870) v1(202,5870) ; U17.6@132,5870 v1(132,5927) ; v1(312,5870) v1(452,5870) ; v1(382,5800) v1(382,5927) ; v1(1901.4,4548.66) 1963.88,4548.66 1963.88,4661.06 2005.14,4702.32 U18.2@2072.07,4702.32 ; v1(2005.14,4639.84) v1(2005.14,4764.8) ; v1(2072.07,4639.84) v1(2072.07,4764.8) ; v1(2559,4555) 2623.88,4555 2623.88,4667.4 U15.1@2665.14,4708.66 U15.2@2732.07,4708.66 ; v1(2665.14,4646.18) v1(2665.14,4771.14) ; v1(2732.07,4646.18) v1(2732.07,4771.14) ; R28.1@3057.4,1559.84 v1(3057.4,1612.44) ; v1(3197.88,1965) v1(3322.84,1965) ; v1(3197.88,2115) v1(3322.84,2115)
  Top Layer w40: C44.1@150,5200.98 C47.1@825,5200.98
  Bottom Layer w8: v1(1044,2130.85) 1082.24,2092.61 C31.2@1087,2092.61 C31.2@1101.76,2077.85 ; C6.2@1490,1038.39 L2.2@1490,1128.82 1560.82,1128.82 1593,1161 1593,1216 1598.99,1221.99 R7.4@1656,1221.99 ; v1(1608.39,1911.61) C26.1@1608.39,1960 ; v1(1682.36,2042.36) 1700,2060 C27.1@1731.61,2060 ; C7.2@1730,1058.39 1800.43,1128.82 L1.2@1830,1128.82
  Bottom Layer w12: R36.2@1140,617.4 v1(1188.4,617.4) ; R5.2@2090,617.4 v1(2090,663)
  Bottom Layer w14: v1(140.71,2055.71) 140.71,2022.68 C28.1@150,2013.39
  Bottom Layer w15: v2(288.39,2115.75) 300,2127.36 C29.1@300,2236.61
  Bottom Layer w20: FR1.1@658.46,175 v1(695,175)
  Bottom Layer w25: v1(382,5800.12) C50.1@452,5800.12 v1(452,5870.12)
  other v1: 1490,1087 1775.72,1104.11 595.61,2094 674,2264
  other v3: 262,5200.98 487,5200.98 712,5200.98
VREF: C3.2 C22.2 C24.1 C25.2 R27.2 U3.6 U5.3 U11.5 | length 1943.7
  Top Layer w8: C24.1@994,1645.61 C25.2@1154,1645.61 ; v1(1114,1604) 1114,1644 ; U11.5@1116.36,1199 C22.2@1220.61,1199
  Top Layer w15: U3.6@250,1452.36 U5.3@250,1572.64
  Bottom Layer w15: v2(250,1512.64) 250,1413.39 464.39,1199 1039,1199 1114,1274 ; v1(1114,1604) 1114,1274 ; v1(1189,1199) 1114,1274
pads on no net: DS1.0 DS3.0 J1.7 J1.23 J1.24 P1.89 P1.90 P2.89 P2.90 P3.11 P3.13 P6.12 P6.14 R6.3 R32.2 R34.1 S1.3 S1.4 U1.A3 U1.A4 U1.A5 U1.A7 U1.A11 U1.A12 U1.A15 U1.B4 U1.B5 U1.B6 U1.B9 U1.B11 U1.B15 U1.B18 U1.C5 U1.C8 U1.C12 U1.C15 U1.D3 U1.D4 U1.D6 U1.D8 U1.D12 U1.D13 U1.D18 U1.E6 U1.E13 U1.E17 U1.E18 U1.F4 U1.F5 U1.F10 U1.G1 U1.G9 U1.G10 U1.G18 U1.H13 U1.H18 U1.J6 U1.J7 U1.K2 U1.K7 U1.K17 U1.K18 U1.L13 U1.L14 U1.M1 U1.N1 U1.N2 U1.N17 U1.P9 U1.P15 U1.P16 U1.R1 U1.R4 U1.R7 U1.R11 U1.R17 U1.T4 U1.T7 U1.T11 U1.U1 U1.U3 U1.U4 U1.U6 U1.U8 U1.U10 U1.U11 U1.U13 U1.V3 U1.V4 U1.V7 U1.V8 U1.V16 U3.1 U3.3 U3.5 U3.7 U3.8 U4.1 U8.1 U8.4 U9.6 U9.8 U10.2 U13.1 U13.3 U13.5 U13.9 U13.10 U13.14 U13.16 U13.18 U13.25 U13.26 U13.27 U13.29 U13.32 U13.33 U13.35 U13.37 U13.39 U13.40 U13.41 U13.42 U13.43 U13.44 U13.47 U13.48
copper on no net: | length 137.8
  Bottom Layer w6: 2539.37,3287.4 2677.17,3287.4

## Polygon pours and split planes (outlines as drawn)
12V on Top Layer "12V" (solid, pour order 1001): 800,5650 1800,5650 1800,5850 2025,5850 2025,5300 1929.3,5300.85 1510,5300 1510,5450 800,5450
P10V on Mid-Layer 2 "P10" (solid, pour order 1002): 75,50 75,3000 1250,3000 1250,50
AGND on MidLayer3 "AGND" (solid, pour order 1002): 75,216.54 75,3000 1250,3000 1250,216.54
SH0 on MidLayer3 "S0" (solid, pour order 1003): 1300,50 1300,1750 2050,1750 2050,50
SH0 on MidLayer3 "SHLD" (solid, pour order 1000): 50,50 50,200 3350,200 3350,50 50,50
GND on GND (split plane): 3379.61,20.39 20.39,20.39 20.39,5979.61 3379.61,5979.61
VDD on VDD (split plane): 3379.61,20.39 20.39,20.39 20.39,5979.61 3379.61,5979.61
VCCINT on VDD (split plane): 3012.26,4105.28 2515.99,3609.01 2513.23,3604.88 2512.26,3600 2512.26,2905.28 2269.72,2662.74 2099.35,2662.74 2099.35,2999.99 2098.38,3004.87 2095.62,3009.01 2091.48,3011.77 2086.6,3012.74 1712.74,3012.74 1712.74,3944.72 1905.28,4137.26 2650,4137.26 2654.88,4138.23 2659.01,4140.99 2809.01,4290.99 2811.77,4295.12 2812.74,4300 2812.74,4837.26 3012.26,4837.26
VCCAUX on VCCAUX (split plane): 3379.61,20.39 20.39,20.39 20.39,5979.61 3379.61,5979.61

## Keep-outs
Keep-Out Layer:
  lines w10: 40,30 40,400 50,400 50,5950 3350,5950 3350,400 3360,400 3360,30 3000,30 3000,50 400,50 400,30 40,30

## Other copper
Top Layer:
  rectangle net GND: 2510,4875 3085,5225
  rectangle net GND: 1850,4875 2525,5225
  pour cut-out: 1100,5950 1050,5900 1050,5700 1100,5650 1300,5650 1350,5700 1350,5900 1300,5950 1100,5950
Bottom Layer:
  rectangle net GND: 2510,4875 3085,5225
  rectangle net GND: 1850,4875 2525,5225
VDD (plane layer: these items are gaps in the copper):
  lines w25: 2086.61,2999.99 2086.61,2650 2275,2650 2525,2900 2525,3600 3025,4100 3025,4850 2800,4850 2800,4300 2650,4150 1900,4150 1700,3950 1700,3000 2086.6,3000 ; 2086.6,3000 2086.61,2999.99

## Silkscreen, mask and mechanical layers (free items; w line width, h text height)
Top Overlay:
  circle w30: c976,4759 r15
  rectangle: 2052.71,2325 2975,2658.65
  lines w9: 350,2600 402,2600 ; 364,2581 387,2581 ; 375,2563 376,2563 ; 375,2600 375,2625 ; 600,1570 600,1830 ; 1275,4400 1327,4400 ; 1289,4381 1312,4381 ; 1300,4363 1301,4363 ; 1300,4400 1300,4425
  lines w25: 2462.32,5882.83 2580.43,5882.83 ; 2521.38,5823.77 2521.38,5941.88 ; 2688.7,5882.83 2806.81,5882.83
  text "+12V" at 2950,5600 h100 r90
  text "12V" at 610,4360 h100
  text "VDD" at 800,4360 h100
  text "AUX" at 1020,4360 h100
  text "SW1/2" at 1792.24,3999.1 h25 r90
  text "PWRSYNC" at 1831.61,3999.1 h25 r90
  text "SW3/4" at 1870.98,3999.1 h25 r90
  text "SW5/6" at 1910.35,3999.1 h25 r90
  text "SW7/8" at 1949.72,3999.1 h25 r90
  text "CFG_SO/CS" at 2323.74,3999.1 h25 r90
  text "CFG_CLK/SI" at 2363.11,3999.1 h25 r90
  text "INT" at 2505,3965 h100
  text "STDO/STMS" at 2700.87,3110.31 h25
  text "STDI" at 2700.87,3070.94 h25
  text "LED" at 2204.72,2795.28 h25 r90
  text "SYNCIN" at 1909.45,2741.14 h25 r90
  text "OSCCLK" at 2066.93,2739.17 h25 r90
  text "SYNCOUT" at 1870.08,2715.55 h25 r90
  text "LOS/STCK" at 2165.35,2669.29 h25 r90
  text "P10V" at 1030,2562 h100
  text "D070071" at 1386.56,2461.92 h180
  text "rev B / serial" at 1392.59,2338.08 h120
  text "Conf" at 2345,2025 h100
  text "CTRL" at 195,660 h100
  text "ERR" at 1020,660 h100
  text "JTAG" at 2539,400 h100
Mechanical 1:
  the board outline again, w15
